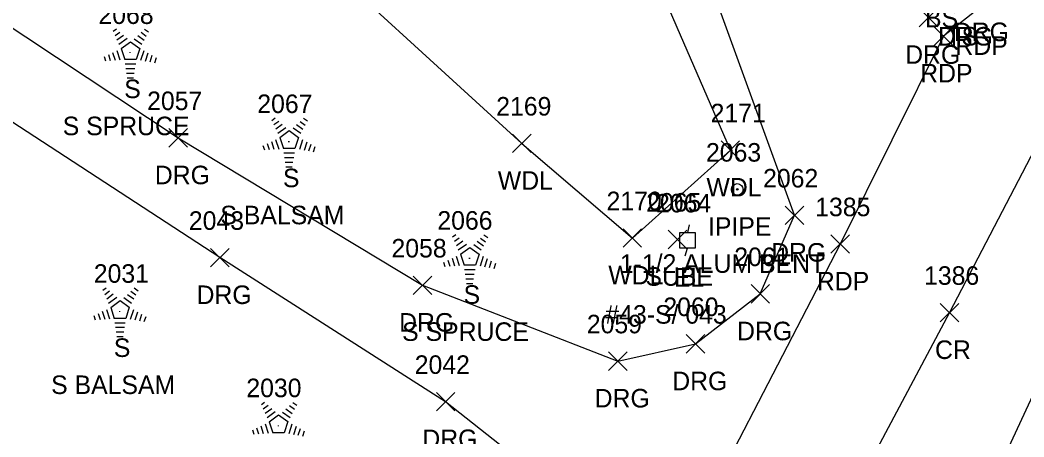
# Model space of a CAD drawing. Extents: x 1885914 to 1887218, y 756253 to 760620.
# Drawn here: x 1886470.3 to 1886578.6, y 760065.4 to 760110.4 of the extents above; entities that cross this region are included whole.
import ezdxf

# ---------------------------------------------------------------- set-up
doc = ezdxf.new("R2010")
doc.units = 0
for name, color, linetype in [('L_A', 7, 'Continuous'), ('L_C', 7, 'Continuous'), ('L_I', 7, 'Continuous'), ('L_TIC', 7, 'Continuous'), ('LAWA', 7, 'Continuous'), ('LTC', 7, 'Continuous'), ('M_A', 7, 'Continuous'), ('M_C', 7, 'Continuous'), ('M_I', 7, 'Continuous'), ('MPIP', 7, 'Continuous'), ('P_A', 7, 'Continuous'), ('P_I', 7, 'Continuous'), ('P_TIC', 7, 'Continuous'), ('PET', 7, 'Continuous'), ('PRC', 7, 'Continuous'), ('R_A', 7, 'Continuous'), ('R_I', 7, 'Continuous'), ('R_TIC', 7, 'Continuous'), ('RDG', 7, 'Continuous'), ('U_A', 7, 'Continuous'), ('U_C', 7, 'Continuous'), ('U_I', 7, 'Continuous'), ('U_TIC', 7, 'Continuous'), ('UEPT', 7, 'Continuous')]:
    doc.layers.add(name, color=color, linetype=linetype)

msp = doc.modelspace()

# ---------------------------------------------------------------- linework, layer by layer
at = {"layer": 'L_TIC'}
for points in [[(1886523.44, 760096.09), (1886525.44, 760098.09)], [(1886525.44, 760096.09), (1886523.44, 760098.09)], [(1886545.94, 760095.36), (1886547.94, 760097.36)], [(1886547.94, 760095.36), (1886545.94, 760097.36)], [(1886535.37, 760085.88), (1886537.37, 760087.88)], [(1886537.37, 760085.88), (1886535.37, 760087.88)]]:
    msp.add_lwpolyline(points, dxfattribs=at)
at = {"layer": 'LAWA'}
msp.add_lwpolyline([(1886410.21, 760202.66), (1886433.18, 760175.41), (1886448.67, 760158.75), (1886465.42, 760144.55), (1886489.64, 760125.96), (1886497.6, 760121.62), (1886524.44, 760097.09), (1886536.37, 760086.88), (1886546.94, 760096.36), (1886535.34, 760123.1)], dxfattribs=at)
at = {"layer": 'LTC'}
for p, q in [((1886480.38, 760109.18), (1886480.73, 760109.44)), ((1886480.58, 760108.71), (1886481.11, 760109.1)), ((1886483.4, 760109.07), (1886483.95, 760108.67)), ((1886483.77, 760109.42), (1886484.19, 760109.12)), ((1886480.79, 760108.25), (1886481.5, 760108.76)), ((1886481, 760107.78), (1886481.88, 760108.42)), ((1886481.23, 760107.33), (1886482.24, 760108.06)), ((1886482.24, 760108.06), (1886483.24, 760107.34)), ((1886482.66, 760108.38), (1886483.47, 760107.79)), ((1886483.03, 760108.72), (1886483.71, 760108.23)), ((1886479.86, 760106.68), (1886480.07, 760106.02)), ((1886480.32, 760106.89), (1886480.59, 760106.06)), ((1886480.77, 760107.11), (1886481.1, 760106.09)), ((1886481.23, 760107.33), (1886481.62, 760106.13)), ((1886483.24, 760107.34), (1886482.85, 760106.13)), ((1886483.67, 760107.07), (1886483.34, 760106.03)), ((1886484.12, 760106.82), (1886483.83, 760105.93)), ((1886479.41, 760106.46), (1886479.56, 760105.99)), ((1886482.85, 760106.13), (1886481.62, 760106.13)), ((1886482.81, 760105.63), (1886481.66, 760105.63)), ((1886484.56, 760106.57), (1886484.33, 760105.84)), ((1886485.01, 760106.32), (1886484.82, 760105.74)), ((1886482.72, 760105.13), (1886481.74, 760105.13)), ((1886482.64, 760104.63), (1886481.81, 760104.63)), ((1886482.56, 760104.13), (1886481.88, 760104.13)), ((1886497.5, 760099.57), (1886497.86, 760099.83)), ((1886497.71, 760099.11), (1886498.24, 760099.49)), ((1886497.92, 760098.64), (1886498.62, 760099.15)), ((1886500.16, 760099.12), (1886500.84, 760098.62)), ((1886500.53, 760099.46), (1886501.08, 760099.07)), ((1886500.9, 760099.81), (1886501.32, 760099.51)), ((1886498.13, 760098.18), (1886499.01, 760098.81)), ((1886498.35, 760097.72), (1886499.37, 760098.46)), ((1886499.37, 760098.46), (1886500.36, 760097.73)), ((1886499.79, 760098.77), (1886500.6, 760098.18)), ((1886496.99, 760097.07), (1886497.2, 760096.42)), ((1886497.44, 760097.29), (1886497.72, 760096.45)), ((1886497.9, 760097.5), (1886498.23, 760096.48)), ((1886498.35, 760097.72), (1886498.74, 760096.53)), ((1886500.36, 760097.73), (1886499.97, 760096.53)), ((1886500.8, 760097.46), (1886500.46, 760096.42)), ((1886501.25, 760097.21), (1886500.96, 760096.32)), ((1886501.69, 760096.96), (1886501.45, 760096.23)), ((1886496.53, 760096.85), (1886496.69, 760096.38)), ((1886499.97, 760096.53), (1886498.74, 760096.53)), ((1886499.93, 760096.03), (1886498.79, 760096.03)), ((1886502.13, 760096.71), (1886501.95, 760096.13)), ((1886499.85, 760095.53), (1886498.86, 760095.53)), ((1886499.77, 760095.03), (1886498.93, 760095.03)), ((1886499.68, 760094.53), (1886499.01, 760094.53)), ((1886516.98, 760086.99), (1886517.33, 760087.25)), ((1886520.37, 760087.23), (1886520.79, 760086.93)), ((1886517.19, 760086.53), (1886517.71, 760086.91)), ((1886517.4, 760086.06), (1886518.1, 760086.57)), ((1886517.6, 760085.59), (1886518.48, 760086.23)), ((1886519.26, 760086.19), (1886520.07, 760085.6)), ((1886519.63, 760086.53), (1886520.31, 760086.04)), ((1886520, 760086.88), (1886520.55, 760086.48)), ((1886517.83, 760085.14), (1886518.84, 760085.87)), ((1886517.83, 760085.14), (1886518.22, 760083.95)), ((1886518.84, 760085.87), (1886519.84, 760085.15)), ((1886519.84, 760085.15), (1886519.45, 760083.95)), ((1886516.01, 760084.27), (1886516.16, 760083.8)), ((1886516.46, 760084.49), (1886516.68, 760083.83)), ((1886516.92, 760084.7), (1886517.19, 760083.87)), ((1886517.37, 760084.92), (1886517.71, 760083.9)), ((1886519.45, 760083.95), (1886518.22, 760083.95)), ((1886520.28, 760084.88), (1886519.94, 760083.84)), ((1886520.72, 760084.63), (1886520.43, 760083.74)), ((1886521.16, 760084.38), (1886520.93, 760083.65)), ((1886521.61, 760084.13), (1886521.42, 760083.55)), ((1886519.41, 760083.45), (1886518.26, 760083.45)), ((1886519.32, 760082.95), (1886518.34, 760082.95)), ((1886519.24, 760082.45), (1886518.41, 760082.45)), ((1886519.16, 760081.95), (1886518.48, 760081.95)), ((1886479.26, 760081.26), (1886479.61, 760081.51)), ((1886479.47, 760080.79), (1886480, 760081.17)), ((1886479.68, 760080.32), (1886480.38, 760080.84)), ((1886481.91, 760080.8), (1886482.59, 760080.31)), ((1886482.28, 760081.15), (1886482.83, 760080.75)), ((1886482.66, 760081.5), (1886483.07, 760081.19)), ((1886479.89, 760079.86), (1886480.76, 760080.5)), ((1886480.11, 760079.4), (1886481.12, 760080.14)), ((1886481.12, 760080.14), (1886482.12, 760079.41)), ((1886481.54, 760080.45), (1886482.35, 760079.86)), ((1886478.29, 760078.53), (1886478.44, 760078.07)), ((1886478.75, 760078.75), (1886478.96, 760078.1)), ((1886479.2, 760078.97), (1886479.47, 760078.13)), ((1886479.66, 760079.18), (1886479.99, 760078.17)), ((1886480.11, 760079.4), (1886480.5, 760078.21)), ((1886482.12, 760079.41), (1886481.73, 760078.21)), ((1886482.56, 760079.14), (1886482.22, 760078.1)), ((1886483, 760078.89), (1886482.71, 760078.01)), ((1886483.45, 760078.64), (1886483.21, 760077.91)), ((1886481.73, 760078.21), (1886480.5, 760078.21)), ((1886481.69, 760077.71), (1886480.55, 760077.71)), ((1886483.89, 760078.39), (1886483.7, 760077.82)), ((1886481.61, 760077.21), (1886480.62, 760077.21)), ((1886481.52, 760076.71), (1886480.69, 760076.71)), ((1886481.44, 760076.21), (1886480.76, 760076.21)), ((1886496.36, 760068.91), (1886496.71, 760069.17)), ((1886496.57, 760068.45), (1886497.1, 760068.83)), ((1886499.38, 760068.81), (1886499.93, 760068.41)), ((1886499.76, 760069.15), (1886500.18, 760068.85)), ((1886496.78, 760067.98), (1886497.48, 760068.49)), ((1886496.99, 760067.52), (1886497.86, 760068.15)), ((1886497.21, 760067.06), (1886498.22, 760067.8)), ((1886498.22, 760067.8), (1886499.22, 760067.07)), ((1886498.64, 760068.11), (1886499.45, 760067.52)), ((1886499.01, 760068.46), (1886499.69, 760067.96)), ((1886496.3, 760066.63), (1886496.57, 760065.79)), ((1886496.76, 760066.84), (1886497.09, 760065.82)), ((1886497.21, 760067.06), (1886497.6, 760065.87)), ((1886499.22, 760067.07), (1886498.83, 760065.87)), ((1886499.66, 760066.8), (1886499.32, 760065.76)), ((1886495.39, 760066.19), (1886495.54, 760065.72)), ((1886495.85, 760066.41), (1886496.06, 760065.76)), ((1886498.83, 760065.87), (1886497.6, 760065.87)), ((1886500.1, 760066.55), (1886499.81, 760065.66)), ((1886500.55, 760066.3), (1886500.31, 760065.57)), ((1886500.99, 760066.05), (1886500.8, 760065.47))]:
    msp.add_line(p, q, dxfattribs=at)
at = {"layer": 'MPIP'}
for radius in [0.625, 0.0833]:
    msp.add_circle((1886547.69, 760092.12), radius, dxfattribs=at)
at = {"layer": 'P_TIC'}
for points in [[(1886568.92, 760107.66), (1886570.92, 760109.66)], [(1886570.92, 760107.66), (1886568.92, 760109.66)], [(1886557.78, 760085.23), (1886559.78, 760087.23)], [(1886559.78, 760085.23), (1886557.78, 760087.23)], [(1886569.57, 760077.83), (1886571.57, 760079.83)], [(1886571.57, 760077.83), (1886569.57, 760079.83)]]:
    msp.add_lwpolyline(points, dxfattribs=at)
at = {"layer": 'PET'}
for points in [[(1886697.38, 760351.34), (1886683.55, 760324.32), (1886670.92, 760299), (1886655.54, 760267.57), (1886637.84, 760233.45), (1886621.76, 760202.26), (1886604.96, 760170.92), (1886588.13, 760139.08), (1886573.73, 760111.63), (1886569.92, 760108.66), (1886558.78, 760086.23), (1886539.06, 760048.09), (1886538, 760043.12), (1886529.58, 760026.84), (1886519.95, 760007.47), (1886505.21, 759975.04), (1886485.32, 759931.76)], [(1886719.61, 760339.51), (1886705.93, 760312.96), (1886693.41, 760288.8), (1886676.56, 760255.91), (1886659.38, 760222.81), (1886642.61, 760189.88), (1886625.62, 760158.68), (1886608.91, 760127.1), (1886594.01, 760097.91), (1886581.16, 760073.4), (1886568, 760045.02), (1886556.6, 760025.44), (1886542.61, 759998.54), (1886526.14, 759964.92), (1886507.07, 759922.75)]]:
    msp.add_lwpolyline(points, dxfattribs=at)
at = {"layer": 'PRC'}
msp.add_lwpolyline([(1886708.51, 760345.16), (1886695.27, 760318.5), (1886682.3, 760293.2), (1886665.98, 760261.32), (1886649.02, 760227.78), (1886632.44, 760196.03), (1886615.49, 760164.09), (1886599.17, 760133.16), (1886583.22, 760103.13), (1886570.57, 760078.83), (1886555.85, 760051.11), (1886540.62, 760021), (1886531.87, 760002.72), (1886516.05, 759969.43), (1886496.99, 759926.69)], dxfattribs=at)
at = {"layer": 'R_TIC'}
for points in [[(1886567.3, 760109.67), (1886569.3, 760111.67)], [(1886569.3, 760109.67), (1886567.3, 760111.67)], [(1886486.38, 760096.68), (1886488.38, 760098.68)], [(1886488.38, 760096.68), (1886486.38, 760098.68)], [(1886552.86, 760088.33), (1886554.86, 760090.33)], [(1886554.86, 760088.33), (1886552.86, 760090.33)], [(1886490.88, 760083.76), (1886492.88, 760085.76)], [(1886492.88, 760083.76), (1886490.88, 760085.76)], [(1886512.73, 760080.78), (1886514.73, 760082.78)], [(1886514.73, 760080.78), (1886512.73, 760082.78)], [(1886549.17, 760079.85), (1886551.17, 760081.85)], [(1886551.17, 760079.85), (1886549.17, 760081.85)], [(1886542.18, 760074.46), (1886544.18, 760076.46)], [(1886544.18, 760074.46), (1886542.18, 760076.46)], [(1886533.81, 760072.6), (1886535.81, 760074.6)], [(1886535.81, 760072.6), (1886533.81, 760074.6)], [(1886515.23, 760068.22), (1886517.23, 760070.22)], [(1886517.23, 760068.22), (1886515.23, 760070.22)]]:
    msp.add_lwpolyline(points, dxfattribs=at)
at = {"layer": 'RDG'}
for points in [[(1886454.48, 760119.53), (1886487.38, 760097.68), (1886513.73, 760081.78), (1886534.81, 760073.6), (1886543.18, 760075.46), (1886550.17, 760080.85), (1886553.86, 760089.33), (1886543.64, 760117.47), (1886531.81, 760149.73), (1886525.16, 760171.12), (1886518.53, 760180.07), (1886498.07, 760192.32), (1886477.19, 760203.32), (1886461.39, 760213.36)], [(1886535.57, 760041.14), (1886534.93, 760050.62), (1886528.91, 760059.18), (1886516.23, 760069.22), (1886491.88, 760084.76), (1886462.81, 760103.73), (1886439.22, 760117.89), (1886425.17, 760124.99), (1886402.51, 760125.72), (1886387.36, 760112.61), (1886362.97, 760090.43), (1886346.71, 760087.42)]]:
    msp.add_lwpolyline(points, dxfattribs=at)
at = {"layer": 'U_TIC'}
for points in [[(1886540.24, 760085.73), (1886542.24, 760087.73)], [(1886542.24, 760085.73), (1886540.24, 760087.73)]]:
    msp.add_lwpolyline(points, dxfattribs=at)
at = {"layer": 'UEPT'}
for p, q in [((1886542.48, 760088.3), (1886542.31, 760087.47)), ((1886541.48, 760085.8), (1886541.48, 760087.47)), ((1886541.48, 760087.47), (1886543.14, 760087.47)), ((1886543.14, 760087.47), (1886543.14, 760085.8)), ((1886542.31, 760086.64), (1886542.31, 760086.64)), ((1886543.14, 760085.8), (1886541.48, 760085.8)), ((1886542.06, 760084.97), (1886542.31, 760085.8))]:
    msp.add_line(p, q, dxfattribs=at)

# ---------------------------------------------------------------- texts
at = {"layer": 'L_A'}
for s, p in [('BS', (1886567.93, 760109.6)), ('TS', (1886570.24, 760107.64)), ('S', (1886481.57, 760101.97)), ('S', (1886498.69, 760092.36)), ('WDL', (1886521.86, 760092.09)), ('WDL', (1886544.36, 760091.36)), ('WDL', (1886533.78, 760081.88)), ('S', (1886518.17, 760079.78)), ('S', (1886480.45, 760074.05))]:
    msp.add_text(s, height=2, dxfattribs=at).set_placement(p)
at = {"layer": 'L_C'}
for s, p in [('S SPRUCE', (1886474.94, 760097.97)), ('S BALSAM', (1886491.94, 760088.36)), ('S SPRUCE', (1886511.54, 760075.78)), ('S BALSAM', (1886473.69, 760070.05))]:
    msp.add_text(s, height=2, dxfattribs=at).set_placement(p)
at = {"layer": 'L_I'}
for s, p in [('2068', (1886478.79, 760109.97)), ('2067', (1886495.92, 760100.36)), ('2169', (1886521.69, 760100.09)), ('2171', (1886544.81, 760099.36)), ('2170', (1886533.59, 760089.88)), ('2066', (1886515.34, 760087.78)), ('2031', (1886478.29, 760082.05)), ('2030', (1886494.74, 760069.71))]:
    msp.add_text(s, height=2, dxfattribs=at).set_placement(p)
at = {"layer": 'LTC'}
for p in [(1886482.12, 760107.08), (1886499.25, 760097.47), (1886518.72, 760084.89), (1886481, 760079.15), (1886498.11, 760066.81)]:
    msp.add_text('.', height=1.04, rotation=270, dxfattribs=at).set_placement(p)
at = {"layer": 'M_A'}
msp.add_text('IPIPE', height=2, dxfattribs=at).set_placement((1886544.53, 760087.12))
at = {"layer": 'M_C'}
msp.add_text('1-1/2 ALUM BENT', height=2, dxfattribs=at).set_placement((1886535.02, 760083.12))
at = {"layer": 'M_I'}
msp.add_text('2063', height=2, dxfattribs=at).set_placement((1886544.31, 760095.12))
at = {"layer": 'P_A'}
for s, p in [('RDP', (1886571.21, 760106.63)), ('RDP', (1886567.41, 760103.66)), ('RDP', (1886556.27, 760081.23)), ('CR', (1886569.01, 760073.83))]:
    msp.add_text(s, height=2, dxfattribs=at).set_placement(p)
at = {"layer": 'P_I'}
for s, p in [('1385', (1886556.09, 760089.23)), ('1386', (1886567.83, 760081.83))]:
    msp.add_text(s, height=2, dxfattribs=at).set_placement(p)
at = {"layer": 'R_A'}
for p in [(1886571.04, 760108.12), (1886569.32, 760107.64), (1886565.79, 760105.67), (1886484.87, 760092.68), (1886551.34, 760084.33), (1886489.37, 760079.76), (1886511.22, 760076.78), (1886547.66, 760075.85), (1886540.67, 760070.46), (1886532.3, 760068.6), (1886513.72, 760064.22)]:
    msp.add_text('DRG', height=2, dxfattribs=at).set_placement(p)
at = {"layer": 'R_I'}
for s, p in [('2057', (1886484.04, 760100.68)), ('2062', (1886550.47, 760092.33)), ('2043', (1886488.54, 760087.76)), ('2058', (1886510.39, 760084.78)), ('2061', (1886547.36, 760083.85)), ('2060', (1886539.71, 760078.46)), ('2059', (1886531.46, 760076.6)), ('2042', (1886512.9, 760072.22))]:
    msp.add_text(s, height=2, dxfattribs=at).set_placement(p)
at = {"layer": 'U_A'}
for s, p in [('SUBE', (1886537.78, 760081.73)), ('EL', (1886540.85, 760081.64))]:
    msp.add_text(s, height=2, dxfattribs=at).set_placement(p)
at = {"layer": 'U_C'}
msp.add_text('#43-S/ 043', height=2, dxfattribs=at).set_placement((1886533.46, 760077.64))
at = {"layer": 'U_I'}
for s, p in [('2065', (1886537.86, 760089.73)), ('2064', (1886538.92, 760089.64))]:
    msp.add_text(s, height=2, dxfattribs=at).set_placement(p)

doc.saveas('drawing.dxf')
